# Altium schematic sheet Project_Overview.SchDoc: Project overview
size A4; Date: Not used; ApprovedBy: Not used; CheckedBy: Not used; Author: Not used; CompanyName: STMicroelectronics; DrawnBy: Not used; Engineer: Not used; Organization: Not used; Address1: Not used; Address2: Not used; Address3: Not used; Address4: Not used; DocumentNumber: MB1191; Revision: Not used; SheetNumber: 1; SheetTotal: 14
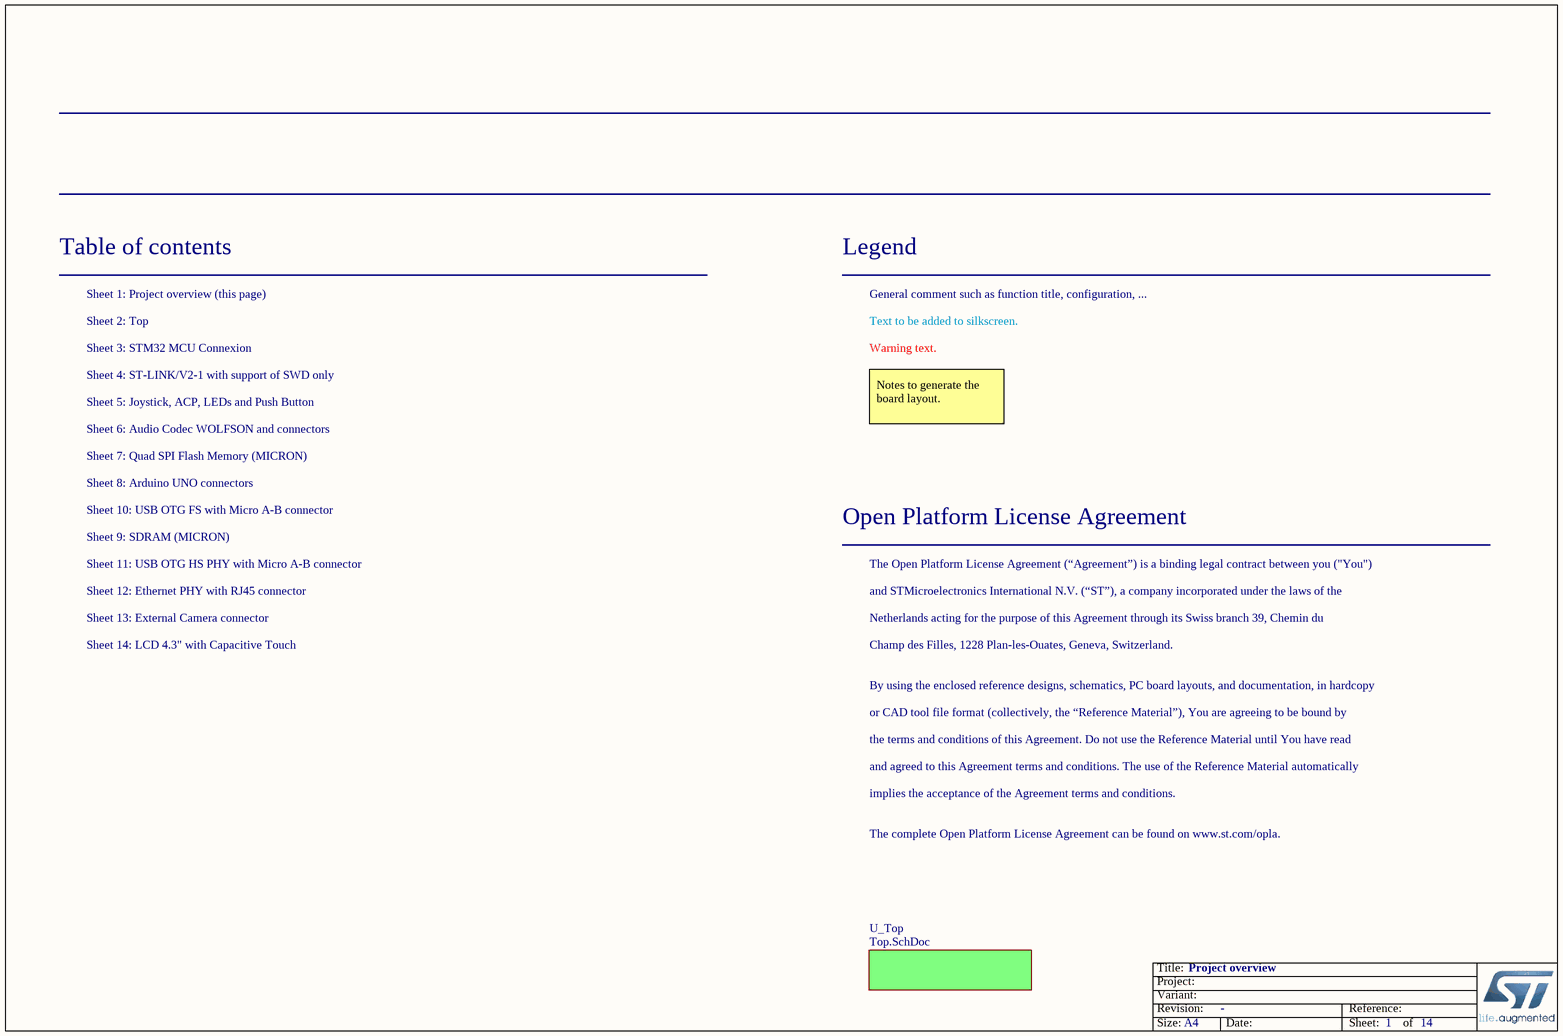
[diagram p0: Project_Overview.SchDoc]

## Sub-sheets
U_Top = Top.SchDoc: no entries

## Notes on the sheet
- Table of contents
- Sheet 1: Project overview (this page)
- Legend
- General comment such as function title, configuration, ...
- Sheet 2: Top
- Sheet 4: ST-LINK/V2-1 with support of SWD only
- Sheet 3: STM32 MCU Connexion
- Text to be added to silkscreen.
- Warning text.
- Sheet 5: Joystick, ACP, LEDs and Push Button
- Sheet 6: Audio Codec WOLFSON and connectors
- Notes to generate the board layout.
- Sheet 8: Arduino UNO connectors
- Sheet 10: USB OTG FS with Micro A-B connector
- Sheet 7: Quad SPI Flash Memory (MICRON)
- Sheet 9: SDRAM (MICRON)
- Sheet 11: USB OTG HS PHY with Micro A-B connector
- Open Platform License Agreement
- The Open Platform License Agreement (“Agreement”) is a binding legal contract between you ("You")
- Sheet 12: Ethernet PHY with RJ45 connector
- Sheet 13: External Camera connector
- Sheet 14: LCD 4.3" with Capacitive Touch
- and STMicroelectronics International N.V. (“ST”), a company incorporated under the laws of the
- Netherlands acting for the purpose of this Agreement through its Swiss branch 39, Chemin du
- Champ des Filles, 1228 Plan-les-Ouates, Geneva, Switzerland.
- By using the enclosed reference designs, schematics, PC board layouts, and documentation, in hardcopy
- or CAD tool file format (collectively, the “Reference Material”), You are agreeing to be bound by
- the terms and conditions of this Agreement. Do not use the Reference Material until You have read
- and agreed to this Agreement terms and conditions. The use of the Reference Material automatically
- implies the acceptance of the Agreement terms and conditions.
- The complete Open Platform License Agreement can be found on www.st.com/opla.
